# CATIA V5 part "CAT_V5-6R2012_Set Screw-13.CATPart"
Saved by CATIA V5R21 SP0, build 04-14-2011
Part number: Set Screw-13
Bounding box of the stored display mesh (mm): x -5.916 to 5.916, y -5.998 to 5.998, z -1.5 to 16
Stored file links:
  D:\CATIA V5R21 E-RESOURCES\CATIA-V5R21\catia-v5r21-prt\c16-catia-v5r20-prt\c16-catia-v5r21-tut01\CAT_V5R21_Set Screw-13.CATPart
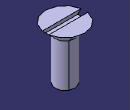
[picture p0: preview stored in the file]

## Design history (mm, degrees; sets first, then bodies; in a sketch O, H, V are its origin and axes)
Body1 (main body)
  Sketch1 on yz-plane, origin (0, 0, 0), H (0, 1, 0), V (0, 0, 1)
    point P1 (0, -1.5)
    line L1 (0, -1.5) -> (3, 0)
    point P2 (3, 0)
    line L2 (3, 0) -> (3, 13)
    line L3 (3, 13) -> (6, 16)
    point P4 (6, 16)
    line L4 (6, 16) -> (0, 16)
    point P5 (0, 16)
    line L5 (0, 16) -> (0, -1.5)
    length L2 = 13
    distance L2 L5 = 3
    distance H P1 = 1.5
    distance P4 L5 = 6
    angle L3 L5 = 45
    coincidence: P1 V, P2 H, P5 V
    vertical: L2 V, L5 V
    horizontal: L4 H
  Shaft1: profile Sketch1, axis edge of Sketch1, angle 360
  Sketch2 on yz-plane, origin (0, 0, 0), H (0, 1, 0), V (0, 0, 1)
    line L1 (-1, 16) -> (1, 16)
    line L2 (1, 16) -> (1, 15)
    line L3 (1, 15) -> (-1, 15)
    line L4 (-1, 15) -> (-1, 16)
    reference projected line E1 (-6, 16) -> (6, 16) from edge of Shaft1
    distance V L2 = 1
    length L1 = 2
    length L2 = 1
    horizontal: L1 H, L3 H
    vertical: L2 V, L4 V
    coincidence: L1 E1
  Pocket1: profile Sketch2, direction (-1, 0, 0), length 16, mirrored extent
